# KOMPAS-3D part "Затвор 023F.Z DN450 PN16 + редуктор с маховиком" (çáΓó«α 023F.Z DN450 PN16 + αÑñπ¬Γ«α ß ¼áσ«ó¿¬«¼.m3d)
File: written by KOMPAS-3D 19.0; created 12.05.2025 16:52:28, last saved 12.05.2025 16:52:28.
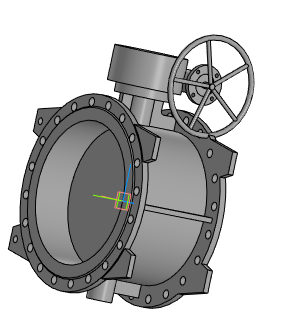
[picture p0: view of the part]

Document properties: Полное имя файла: Затвор 023F.Z DN450 PN16 + редуктор с маховиком.a3d

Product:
- Part/product: Затвор 023F.Z DN450 PN16 + редуктор с маховиком
    Масса: 224.891

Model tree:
1. Операция без истории:1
